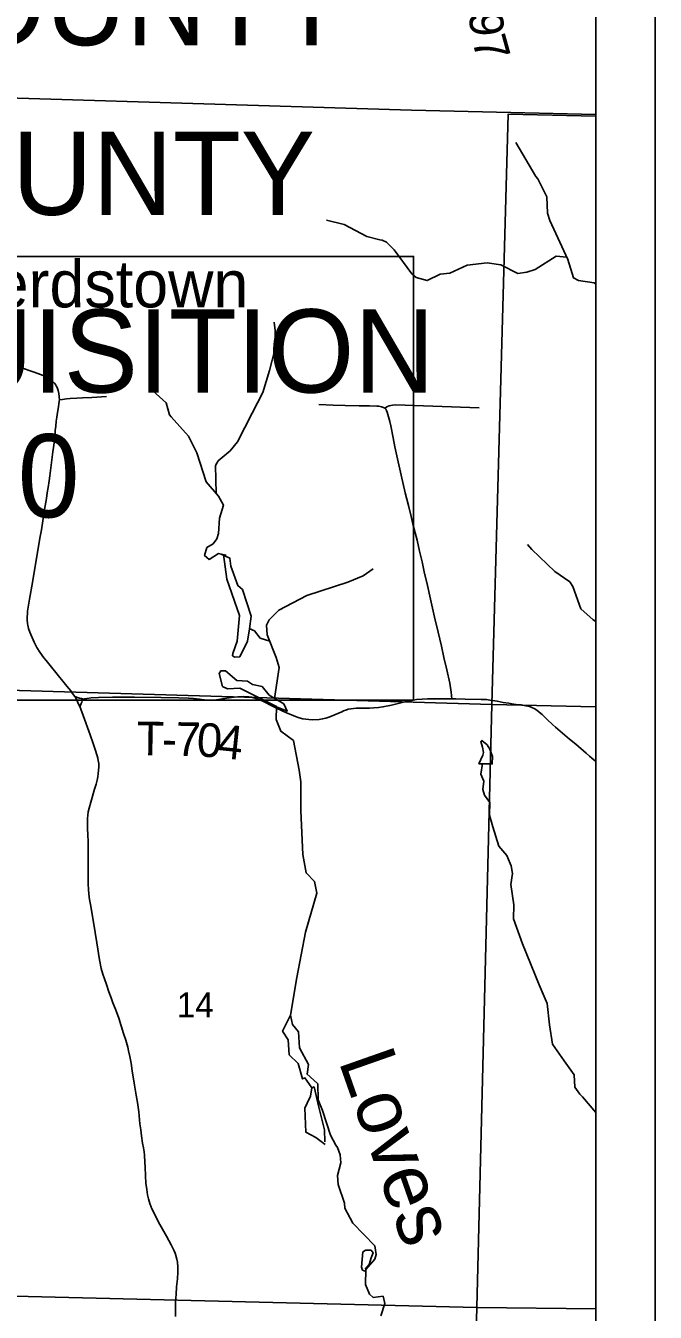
# Model space of a CAD drawing. Extents: x 0 to 34, y 0 to 22.
# Drawn here: x 8.441 to 9.5, y 14.47 to 16.635 of the extents above; entities that cross this region are included whole.
import ezdxf

# ---------------------------------------------------------------- set-up
doc = ezdxf.new("R2010")
doc.units = 0
for name, color, linetype in [('GM_X_Corporation', 7, 'Continuous'), ('GM_X_County', 7, 'Continuous'), ('GM_X_Minor_River', 7, 'Continuous'), ('GM_X_Minor_River_Text', 7, 'Continuous'), ('GM_X_Section_Text', 7, 'Continuous'), ('GM_X_Township_Road', 7, 'Continuous'), ('GM_X_Township_Road_Text', 7, 'Continuous'), ('GM_X_Unincorporated_Text', 7, 'Continuous'), ('SH_Data', 7, 'Continuous'), ('SH_Text', 7, 'Continuous')]:
    doc.layers.add(name, color=color, linetype=linetype)

msp = doc.modelspace()

# ---------------------------------------------------------------- linework, layer by layer
at = {"layer": 'GM_X_Corporation'}
for points in [[(9.4, 16.4853), (9.4, 20.4), (2.6, 20.4), (2.6, 16.6918), (3.1555, 16.6686), (3.1684, 16.6682), (4.0515, 16.6368), (4.1011, 16.6362), (4.1867, 16.6352), (4.5473, 16.6256), (4.6351, 16.6229), (5.4202, 16.5982), (6.0834, 16.5816), (6.2194, 16.578), (8.0963, 16.5226), (9.09, 16.4927)], [(9.4, 16.4853), (9.4, 20.4), (6.2895, 20.4), (6.2595, 19.6124), (6.2942, 19.6131), (6.2926, 19.1539), (6.292, 18.5898), (6.2786, 18.5898), (6.2744, 18.4654), (6.2729, 18.2077), (6.2194, 16.578), (8.0963, 16.5226), (9.09, 16.4927)], [(2.6, 16.6918), (2.6, 13.6), (9.4, 13.6), (9.4, 16.4853), (9.09, 16.4927), (8.0963, 16.5226), (6.2194, 16.578), (6.0834, 16.5816), (5.4202, 16.5982), (4.6351, 16.6229), (4.5473, 16.6256), (4.1867, 16.6352), (4.1011, 16.6362), (4.0515, 16.6368), (3.1684, 16.6682), (3.1555, 16.6686)], [(9.4, 15.4882), (9.4, 16.4822), (9.2526, 16.4858), (9.225, 15.4925)], [(9.225, 15.4925), (9.1998, 14.4779), (8.1927, 14.5025), (8.2216, 15.5221)], [(9.4, 14.4754), (9.4, 15.4882), (9.225, 15.4925), (9.1998, 14.4779)], [(8.1659, 13.6), (9.1765, 13.6), (9.1998, 14.4779), (8.1927, 14.5025)], [(9.1765, 13.6), (9.4, 13.6), (9.4, 14.4754), (9.1998, 14.4779)]]:
    msp.add_lwpolyline(points, close=True, dxfattribs=at)
msp.add_lwpolyline([(4.5781, 13.6), (9.4, 13.6), (9.4, 16.4853), (9.09, 16.4927), (8.0963, 16.5226), (6.2194, 16.578), (6.0834, 16.5816), (5.4202, 16.5982), (4.6351, 16.6229)], dxfattribs=at)
at = {"layer": 'GM_X_County'}
msp.add_lwpolyline([(9.4, 16.4853), (9.09, 16.4927), (8.0963, 16.5226), (6.2194, 16.578), (6.0834, 16.5816), (5.4202, 16.5982), (4.6351, 16.6229), (4.5473, 16.6256), (4.1867, 16.6352), (4.1011, 16.6362), (4.0515, 16.6368), (3.1684, 16.6682), (3.1555, 16.6686), (2.6, 16.6918)], dxfattribs=at)
at = {"layer": 'GM_X_Minor_River'}
for points in [[(9.4, 16.1998), (9.397, 16.2019), (9.3711, 16.2059), (9.3622, 16.2102), (9.3528, 16.2414), (9.3228, 16.307), (9.3187, 16.3194), (9.3177, 16.3466), (9.3022, 16.3769), (9.2991, 16.381), (9.2655, 16.4381)], [(9.3511, 16.245), (9.3333, 16.247), (9.2981, 16.2242), (9.2842, 16.2197), (9.2687, 16.2179), (9.2403, 16.232), (9.217, 16.2356), (9.1833, 16.2318), (9.1544, 16.2182), (9.1381, 16.2163), (9.1163, 16.2056), (9.098, 16.2108), (9.0907, 16.2171), (9.0605, 16.2576), (9.0481, 16.2702), (9.0404, 16.2735), (9.0366, 16.2745), (9.0148, 16.2797), (8.9768, 16.3), (8.947, 16.3076)], [(8.7611, 15.8476), (8.7602, 15.8946), (8.7646, 15.9023), (8.7847, 15.919), (8.7973, 15.9341), (8.8216, 15.9828), (8.8398, 16.0173), (8.8511, 16.0543), (8.8608, 16.0913), (8.8605, 16.1219), (8.8587, 16.1355)], [(8.7697, 15.7452), (8.7651, 15.7462), (8.7494, 15.7364), (8.7417, 15.743), (8.7455, 15.7563), (8.756, 15.763), (8.7623, 15.7711), (8.7655, 15.7803), (8.7668, 15.8057), (8.7735, 15.8278), (8.7652, 15.8428), (8.7445, 15.8669), (8.7286, 15.9158), (8.7147, 15.9439), (8.6858, 15.9762), (8.6827, 15.9799), (8.6773, 16.0002), (8.6545, 16.0201), (8.6523, 16.0322), (8.6491, 16.0541)], [(9.4, 15.6323), (9.3955, 15.6351), (9.375, 15.6536), (9.3616, 15.6912), (9.3561, 15.6986), (9.331, 15.7162), (9.2926, 15.7532), (9.2852, 15.7618)], [(8.7697, 15.7452), (8.7781, 15.7439)], [(8.7697, 15.7452), (8.7843, 15.7387), (8.7861, 15.7251), (8.7979, 15.6924), (8.8056, 15.6858), (8.8203, 15.641), (8.8173, 15.6198)], [(8.8173, 15.6198), (8.8141, 15.5992), (8.801, 15.5724), (8.7927, 15.5718), (8.7888, 15.5744), (8.7895, 15.5782), (8.7966, 15.5992), (8.8005, 15.6421), (8.7794, 15.703), (8.7735, 15.7446)], [(8.8596, 15.5027), (8.8671, 15.5546), (8.8625, 15.5716), (8.8472, 15.6098), (8.8461, 15.6261), (8.8504, 15.6349), (8.8668, 15.6512), (8.914, 15.6758), (8.983, 15.6983), (9.0086, 15.7087), (9.0257, 15.7209)], [(8.8515, 15.5991), (8.8356, 15.6039), (8.8258, 15.6162), (8.8166, 15.6201)], [(8.8629, 15.4886), (8.8805, 15.481), (8.8753, 15.4934), (8.8507, 15.508), (8.8386, 15.5229), (8.8226, 15.5259), (8.8141, 15.5318), (8.7962, 15.5325), (8.7769, 15.5491), (8.7689, 15.5489), (8.7663, 15.5447), (8.7721, 15.5228), (8.7806, 15.5188), (8.8014, 15.5201), (8.8629, 15.489)], [(8.8862, 14.9695), (8.8973, 15.0327), (8.9115, 15.1092), (8.9304, 15.1748), (8.9266, 15.1948), (8.9126, 15.2089), (8.9069, 15.2402), (8.9037, 15.3133), (8.9038, 15.3622), (8.901, 15.3818), (8.8915, 15.4316), (8.8699, 15.4474), (8.8622, 15.4673), (8.8629, 15.489)], [(9.2092, 15.3923), (9.2257, 15.3924), (9.2262, 15.4046), (9.2217, 15.4174), (9.217, 15.4245), (9.2085, 15.4318), (9.2063, 15.4299), (9.2091, 15.4205), (9.2109, 15.4114), (9.2102, 15.4069), (9.2033, 15.3927), (9.2092, 15.3923)], [(9.4, 14.8057), (9.3775, 14.8319), (9.3732, 14.8367), (9.3646, 14.8487), (9.3634, 14.8691), (9.3465, 14.893), (9.3269, 14.9206), (9.3219, 14.9535), (9.3181, 14.989), (9.3048, 15.0209), (9.2767, 15.0896), (9.2617, 15.1317), (9.2619, 15.1553), (9.2569, 15.1893), (9.2599, 15.2079), (9.2574, 15.2207), (9.2561, 15.2249), (9.2501, 15.2384), (9.2369, 15.254), (9.2266, 15.2863), (9.2209, 15.3063), (9.2219, 15.3275), (9.2129, 15.3398), (9.21, 15.3493), (9.2116, 15.3633), (9.2064, 15.3753), (9.2094, 15.3932)], [(8.8862, 14.9695), (8.8731, 14.9427), (8.8826, 14.9281), (8.8839, 14.9031), (8.899, 14.8883), (8.9065, 14.8623), (8.9106, 14.8639), (8.9224, 14.8475)], [(8.9143, 14.8701), (8.9169, 14.8868), (8.9015, 14.9145), (8.9003, 14.9327), (8.9001, 14.9418), (8.89, 14.954), (8.8862, 14.9695)], [(9.0382, 14.4639), (9.045, 14.4846), (9.042, 14.4966), (9.0254, 14.4947), (9.0192, 14.5003), (9.0123, 14.5164), (9.0133, 14.5414), (9.0284, 14.5592), (9.0305, 14.5669), (9.0283, 14.5812), (8.991, 14.6198), (8.9775, 14.6449), (8.9773, 14.6532), (8.9664, 14.6844), (8.9652, 14.6996), (8.9708, 14.7209), (8.9701, 14.7345), (8.9653, 14.7469), (8.9629, 14.7507), (8.9534, 14.7679), (8.94, 14.8093), (8.9327, 14.8269), (8.9321, 14.8538), (8.9131, 14.8712)], [(8.9442, 14.7567), (8.9434, 14.7764), (8.9338, 14.8148), (8.9261, 14.8488), (8.9224, 14.8475), (8.9201, 14.8331), (8.9142, 14.8216), (8.9106, 14.8131), (8.9123, 14.7726), (8.9289, 14.7635), (8.9447, 14.7518)], [(9.0132, 14.5384), (9.0076, 14.5406), (9.0056, 14.5454), (9.008, 14.5713), (9.0129, 14.5744), (9.022, 14.5743), (9.0252, 14.5698), (9.0223, 14.5614), (9.0188, 14.5499), (9.0121, 14.5422)]]:
    msp.add_lwpolyline(points, dxfattribs=at)
at = {"layer": 'GM_X_Township_Road'}
for points in [[(8.5237, 15.5058), (8.5197, 15.5111), (8.5166, 15.5154), (8.5103, 15.5232), (8.5057, 15.5289), (8.482, 15.5582), (8.4752, 15.5664), (8.4713, 15.5711), (8.4649, 15.5806), (8.4594, 15.5885), (8.4549, 15.5971), (8.4477, 15.6142), (8.4455, 15.6202), (8.4443, 15.6256), (8.4439, 15.6283), (8.4436, 15.6354), (8.4442, 15.6495), (8.4473, 15.6697), (8.4521, 15.6979), (8.4549, 15.7153), (8.4622, 15.7581), (8.4648, 15.772), (8.4673, 15.7865), (8.4714, 15.8126), (8.4728, 15.8206), (8.4757, 15.839), (8.4771, 15.8484), (8.4786, 15.8578), (8.4801, 15.869), (8.4815, 15.8773), (8.4868, 15.9174), (8.4891, 15.9359), (8.4897, 15.9425), (8.4907, 15.9537), (8.4914, 15.9605), (8.4923, 15.9689), (8.4934, 15.976), (8.4945, 15.9838), (8.496, 15.9933), (8.4974, 16.0028), (8.4976, 16.0052), (8.4969, 16.0157), (8.4954, 16.0209), (8.4936, 16.0257), (8.4923, 16.0286), (8.4912, 16.0306), (8.4891, 16.0333), (8.4844, 16.0377), (8.4822, 16.0394), (8.478, 16.0421), (8.4752, 16.0437), (8.4676, 16.0471), (8.4537, 16.0524), (8.4341, 16.0587)], [(8.4976, 16.0052), (8.5029, 16.0058), (8.5094, 16.0066), (8.5157, 16.0071), (8.5268, 16.0079), (8.5366, 16.0085), (8.5523, 16.0092), (8.5767, 16.0104)], [(8.9341, 15.9972), (8.9579, 15.9962), (8.9781, 15.9954), (9.002, 15.9952), (9.0191, 15.9949), (9.0316, 15.9945), (9.0351, 15.9942), (9.0395, 15.9934), (9.0429, 15.9924), (9.0449, 15.9911), (9.0498, 15.9938), (9.0522, 15.9948), (9.0552, 15.9956), (9.0578, 15.996), (9.0634, 15.9965), (9.2036, 15.9914)], [(9.1576, 15.5019), (9.1574, 15.5074), (9.1568, 15.5134), (9.1542, 15.528), (9.1492, 15.5508), (9.1445, 15.5713), (9.1402, 15.5903), (9.1346, 15.6139), (9.1287, 15.6394), (9.1219, 15.6697), (9.1167, 15.6924), (9.1113, 15.7157), (9.1077, 15.7322), (9.1036, 15.7506), (9.0992, 15.7687), (9.093, 15.7937), (9.0894, 15.8088), (9.0849, 15.8273), (9.0794, 15.8483), (9.0726, 15.8784), (9.0665, 15.9058), (9.0621, 15.926), (9.0589, 15.9413), (9.0549, 15.9613), (9.0532, 15.9688), (9.0514, 15.9764), (9.0492, 15.9844), (9.0481, 15.9871), (9.0466, 15.9894), (9.0449, 15.9911)], [(8.6928, 14.4625), (8.6929, 14.4794), (8.6931, 14.4883), (8.6938, 14.4993), (8.6948, 14.5127), (8.6961, 14.5261), (8.6966, 14.5369), (8.6968, 14.5453), (8.6963, 14.554), (8.6953, 14.559), (8.6937, 14.5649), (8.6922, 14.5691), (8.6901, 14.5742), (8.6856, 14.5829), (8.6777, 14.5979), (8.6686, 14.6135), (8.6644, 14.621), (8.6579, 14.6341), (8.6532, 14.6439), (8.6498, 14.6526), (8.6473, 14.6606), (8.6458, 14.6673), (8.6445, 14.6762), (8.6431, 14.6869), (8.6423, 14.6992), (8.6416, 14.7137), (8.6412, 14.7225), (8.6405, 14.7339), (8.64, 14.7394), (8.639, 14.7463), (8.6375, 14.7543), (8.6356, 14.7665), (8.6344, 14.7765), (8.633, 14.7866), (8.6311, 14.8067), (8.6289, 14.8229), (8.6269, 14.8349), (8.6241, 14.8517), (8.62, 14.876), (8.6181, 14.8891), (8.6161, 14.8999), (8.6141, 14.9095), (8.6126, 14.9158), (8.6094, 14.9276), (8.6057, 14.9389), (8.5973, 14.9646), (8.5917, 14.9799), (8.5873, 14.9906), (8.5844, 14.9988), (8.5808, 15.0088), (8.5767, 15.0212), (8.5733, 15.0308), (8.5709, 15.0386), (8.5681, 15.048), (8.5653, 15.0625), (8.5604, 15.0914), (8.555, 15.1263), (8.5498, 15.1558), (8.5485, 15.1641), (8.5477, 15.1684), (8.5471, 15.1743), (8.5466, 15.1804), (8.5461, 15.1905), (8.5462, 15.2217), (8.5461, 15.2484), (8.5458, 15.2604), (8.5452, 15.2748), (8.5448, 15.2823), (8.5446, 15.2953), (8.5449, 15.3008), (8.5453, 15.3061), (8.5462, 15.312), (8.5475, 15.3181), (8.5502, 15.328), (8.5569, 15.35), (8.5593, 15.3584), (8.5609, 15.3652), (8.5621, 15.3704), (8.563, 15.376), (8.5636, 15.3814), (8.5639, 15.3877), (8.5637, 15.3932), (8.563, 15.3984), (8.5624, 15.4018), (8.5612, 15.406), (8.5579, 15.4166), (8.5543, 15.4269), (8.5491, 15.4416), (8.5374, 15.4737), (8.5336, 15.4843), (8.5323, 15.4876), (8.53, 15.4932), (8.5276, 15.4987), (8.5251, 15.5034), (8.5237, 15.5058)], [(8.5237, 15.5058), (8.5279, 15.5042), (8.5313, 15.5033), (8.5346, 15.5023), (8.538, 15.5015)], [(8.5323, 15.4876), (8.5332, 15.4912), (8.5341, 15.4938), (8.5351, 15.4962), (8.5361, 15.4984), (8.538, 15.5015), (8.54, 15.5019), (8.5439, 15.5027), (8.5512, 15.5034), (8.5631, 15.5039), (8.587, 15.5045), (8.6241, 15.5048), (8.6686, 15.5044), (8.6986, 15.5036), (8.7147, 15.5029), (8.7231, 15.5024), (8.7333, 15.5014), (8.7455, 15.4999), (8.7509, 15.4995), (8.7587, 15.4998), (8.762, 15.5002), (8.7688, 15.5013), (8.7794, 15.5031), (8.7873, 15.5042), (8.7975, 15.5051), (8.8065, 15.5056), (8.812, 15.5055), (8.8164, 15.5052), (8.8205, 15.5046), (8.8264, 15.5033), (8.8314, 15.5016), (8.8344, 15.5005), (8.8396, 15.498), (8.8456, 15.495), (8.8516, 15.4916), (8.8618, 15.4867), (8.8725, 15.4815), (8.8796, 15.4783), (8.8883, 15.4747), (8.8946, 15.4724), (8.901, 15.4701), (8.9071, 15.4683), (8.9121, 15.4675), (8.9174, 15.4669), (8.9226, 15.4665), (8.9347, 15.4672), (8.9404, 15.4681), (8.9458, 15.4694), (8.9525, 15.4717), (8.9593, 15.4743), (8.966, 15.4772), (8.9727, 15.4801), (8.9757, 15.4816), (8.9794, 15.4831), (8.9832, 15.4843), (8.9882, 15.4852), (8.9922, 15.4856), (8.9967, 15.486), (9.0093, 15.4861), (9.0192, 15.4864), (9.0268, 15.4866), (9.0343, 15.4872), (9.0417, 15.4884), (9.0563, 15.4914), (9.0786, 15.4968), (9.0872, 15.4987), (9.0934, 15.4999), (9.0985, 15.5007), (9.1078, 15.5015), (9.1168, 15.5017), (9.1321, 15.5018), (9.148, 15.5019), (9.1576, 15.5019), (9.1643, 15.5017), (9.1801, 15.5013), (9.2069, 15.501), (9.2159, 15.5006), (9.2215, 15.4999), (9.2264, 15.4993), (9.2341, 15.4979), (9.2442, 15.496), (9.2536, 15.4945), (9.2588, 15.4936), (9.2662, 15.4926), (9.2744, 15.4916), (9.2823, 15.4902), (9.2858, 15.4895), (9.2899, 15.4883), (9.2937, 15.4868), (9.2965, 15.4854), (9.3009, 15.4826), (9.3041, 15.4803), (9.3077, 15.4775), (9.3099, 15.4755), (9.3184, 15.4672), (9.3273, 15.4586), (9.332, 15.4543), (9.3557, 15.4342), (9.3661, 15.4255), (9.3836, 15.4107), (9.3895, 15.4054), (9.3932, 15.4021), (9.4, 15.3962)]]:
    msp.add_lwpolyline(points, dxfattribs=at)
at = {"layer": 'SH_Data'}
for points in [[(2.5, 20.5), (9.5, 20.5), (9.5, 13.5), (2.5, 13.5)], [(2.6, 20.4), (9.4, 20.4), (9.4, 13.6), (2.6, 13.6)]]:
    msp.add_lwpolyline(points, close=True, dxfattribs=at)
at = {"layer": 'SH_Text'}
msp.add_lwpolyline([(7.2376, 16.2463), (9.0934, 16.2463), (9.0934, 15.4999), (7.2376, 15.4999)], close=True, dxfattribs=at)

# ---------------------------------------------------------------- texts
at = {"layer": 'GM_X_Minor_River_Text'}
msp.add_text('Loves', height=0.09462, rotation=289.3644, dxfattribs=at).set_placement((8.9667, 14.8926))
at = {"layer": 'GM_X_Section_Text'}
msp.add_text('14', height=0.04186, rotation=0, dxfattribs=at).set_placement((8.695, 14.966))
at = {"layer": 'GM_X_Township_Road_Text'}
for s, rotation, p in [('9', 274.9285, (9.1863, 16.6565)), ('7', 285.4305, (9.1913, 16.6104)), ('T', 359.1129, (8.6272, 15.407)), ('7', 358.8967, (8.693, 15.406)), ('0', 356.4227, (8.7274, 15.4053)), ('4', 353.9523, (8.7616, 15.4032)), ('-', 359.0788, (8.6697, 15.4063))]:
    msp.add_text(s, height=0.0568, rotation=rotation, dxfattribs=at).set_placement(p)
at = {"layer": 'GM_X_Unincorporated_Text'}
msp.add_text('Shepherdstown', height=0.078977, rotation=0, dxfattribs=at).set_placement((8.0816, 16.1606))
at = {"layer": 'SH_Text'}
for s, p in [('HARRISON COUNTY', (7.1536, 16.6018)), ('BELMONT COUNTY', (7.1802, 16.3163)), ('BEGIN ACQUISITION', (7.2774, 16.0173)), ('STA. 10+30.00', (7.2774, 15.8073))]:
    msp.add_text(s, height=0.14, dxfattribs=at).set_placement(p)

doc.saveas('drawing.dxf')
